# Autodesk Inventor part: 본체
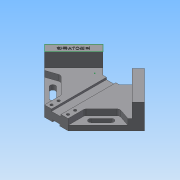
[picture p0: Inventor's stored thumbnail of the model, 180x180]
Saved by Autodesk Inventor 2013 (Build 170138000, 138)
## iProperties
Created: 2019-04
Part Number: 본체
Material: 일반
Document SubType Name: Modeling
Designer: Administrator
Density: 1 g/cm^3
Author: Administrator
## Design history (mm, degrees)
sketch "스케치1"
  geometry: L1 (0, 84.853)-(0, -84.853); L2 (-35.355, 49.497)-(-84.853, 0); L3 (-84.853, 0)-(-20, -64.853); L4 (-20, -64.853)-(0, -64.853); L5 (-35.355, 49.497)-(-14.005, 28.147); L6 (-35.355, 49.497)-(-69.687, 83.829); L7 (0, 28.147)-(-14.005, 28.147); L8 (35.355, 49.497)-(84.853, 0); L9 (35.355, 49.497)-(14.005, 28.147); L10 (0, 28.147)-(14.005, 28.147); L11 (84.853, 0)-(20, -64.853); L12 (20, -64.853)-(0, -64.853); 2 further points
  constraints: 24 end point, 4 symmetric about line, 2 parallel, 2 point on line, 1 coincident, 1 collinear, 1 midpoint, 1 perpendicular, 1 vertical
  dimensions: "d0" = 90 deg angle of L3 L2; "d1" = 120 distance of L1.start L2.end; "d3" = 120 distance of L2.end L1.end; "d4" = 20 distance of L1.end L4.end; "d6" = 50 distance from line of L1.start L6; "d7" = 93 distance of L4.end L7.start
extrude "돌출1" new body sketch "스케치1" distance "d8" = 18; taper "d9" = 0 deg
sketch "스케치2"
  geometry: L1 (-14.005, 28.147)-(-35.355, 49.497) reference; L2 (-35.355, 49.497)-(-84.853, 0) reference; L3 (-84.853, 0)-(-20, -64.853) reference; L4 (-24.749, 38.891)-(-74.246, -10.607); 1 further point
  constraints: 2 end point, 2 point on line, 1 perpendicular
extrude "돌출2" join sketch "스케치2" distance "d12" = 24; taper "d13" = 0 deg
sketch "스케치3"
  geometry: L1 (14.005, 28.147)-(-14.005, 28.147) reference; L2 (-20, -64.853)-(20, -64.853) reference; L3 (-8, 28.147)-(8, 28.147); L4 (8, 28.147)-(8, -64.853); L5 (8, -64.853)-(-8, -64.853); L6 (-8, -64.853)-(-8, 28.147); 2 further points
  constraints: 8 end point, 2 parallel, 2 point on line, 1 horizontal, 1 midpoint, 1 perpendicular, 1 vertical alignment
  dimensions: "d14" = 16 distance of L3.start L3.end
extrude "돌출3" cut sketch "스케치3" distance "d16" = 3.5; taper "d17" = 0 deg
sketch "스케치4"
  geometry: L1 (20, -64.853)-(-20, -64.853) reference; L2 (-14.005, 28.147)-(14.005, 28.147) reference; L3 (-6, 28.147)-(6, 28.147); L4 (6, 28.147)-(6, -64.853); L5 (6, -64.853)-(-6, -64.853); L6 (-6, -64.853)-(-6, 28.147); 2 further points
  constraints: 8 end point, 2 parallel, 2 point on line, 1 horizontal, 1 midpoint, 1 perpendicular, 1 vertical alignment
  dimensions: "d18" = 12 distance of L3.start L3.end
extrude "돌출4" cut sketch "스케치4" distance "d20" = 3; taper "d21" = 0 deg
sketch "스케치5"
  geometry: L1 (-74.246, -10.607)-(-20, -64.853) reference; L2 (-20, -64.853)-(-8, -64.853) reference; L3 (-70.711, -14.142)-(-49.497, -7.071); L4 (-20, -64.853)-(-20, -36.569); L5 (-20, -36.569)-(-49.497, -7.071); L6 (-35.355, 49.497)-(-84.853, 0) reference; 1 further point
  constraints: 6 end point, 1 parallel, 1 perpendicular, 1 point on line
  dimensions: "d22" = 20 distance from line of L3.start L6; "d23" = 20 distance from line of L1 L3.end; "d24" = 30 distance from line of L6 L3.end
extrude "돌출5" cut sketch "스케치5" distance "d25" = 10; taper "d26" = 0 deg
sketch "스케치6"
  geometry: L1 (-20, -64.853)-(-70.711, -14.142) reference; L2 (-35.355, 49.497)-(-84.853, 0) reference; L3 (-52.593, -24.479)-(-35.709, -41.366); L4 (-46.231, -18.118)-(-29.345, -35.002); A1 r 4.5 centre (-49.497, -21.213) between (-46.231, -18.118) and (-52.593, -24.479); A2 r 4.5 centre (-32.527, -38.184) between (-35.709, -41.366) and (-29.345, -35.002); 1 further point
  constraints: 4 end point, 4 point on circle, 2 centre point, 2 tangent
  dimensions: "d27" = 9 diameter of A1; "d28" = 40 distance from line of A1.centre L2; "d29" = 10 distance from line of L1 A1.centre; "d32" = 9 diameter of A2
extrude "돌출6" cut sketch "스케치6" stored distance "d33" = 10; taper "d34" = 0 deg
sketch "스케치7"
  geometry: L1 (-20, -64.853)-(-8, -64.853) reference; C1 r 2.25 at (-14, -58.853); C2 r 2.25 at (-14, -46.853); 1 further point
  constraints: 2 centre point
  dimensions: "d35" = 4.5 diameter of C1; "d36" = 14 horizontal distance of point (0, 0) C1.centre; "d37" = 6 distance from line of L1 C1.centre; "d38" = 4.5 diameter of C2; "d39" = 12 distance of C1.centre C2.centre
extrude "돌출7" cut sketch "스케치7" stored distance "d40" = 10; taper "d41" = 0 deg
sketch "스케치8"
  geometry: C1 r 2.25 at (14, -58.853) reference; C2 r 2.25 at (14, -46.853) reference; C3 r 4 at (14, -58.853); C4 r 4 at (14, -46.853); 1 further point
  constraints: 2 centre point, 2 coincident
  dimensions: "d42" = 8 diameter of C3; "d43" = 8 diameter of C4
extrude "돌출8" cut sketch "스케치8" distance "d44" = 10; taper "d45" = 0 deg
fillet "모깎기1" dims "d47" = 5
sketch "스케치13"
  geometry: L1 (-35.355, 49.497)-(-84.853, 0) reference; L2 (-84.853, 0)-(-74.246, -10.607) reference; L3 (-74.246, -10.607)-(-24.749, 38.891) reference; L4 (-24.749, 38.891)-(-35.355, 49.497) reference; 1 further point
node "작업 평면2"
sketch "스케치14"
  geometry: L1 (-66.62, 2.035)-(-36.524, 32.745); 1 further point
  constraints: 2 end point, 1 other
feature "엠보싱1" sketch "스케치14" dims "d0" = 90 deg, "d1" = 120, "d3" = 120, "d4" = 20, "d6" = 50, "d7" = 93, "d49" = 0.5, "d50" = 0
node "솔리드1"
mirror "대칭1"
mirror "대칭2"
other parameters: "d48" = 183.25
